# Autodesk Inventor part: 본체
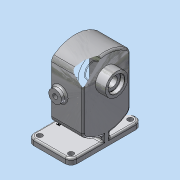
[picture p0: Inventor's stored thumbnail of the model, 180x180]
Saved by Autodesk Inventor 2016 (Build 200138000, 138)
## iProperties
Created: 2019-03
Part Number: 본체
Material: 알루미늄 6061
Document SubType Name: Modeling
Designer: Administrator
Density: 2.7 g/cm^3
Appearance: 알루미늄 - 평지
Mass: 1186.4 g
Surface Area: 720.893 cm^2
Volume: 439.408 cm^3
Author: Administrator
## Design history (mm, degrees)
sketch "스케치1"
  geometry: L1 (-36.5, -60)-(36.5, -60); L2 (36.5, -60)-(36.5, 60); L3 (36.5, 60)-(-36.5, 60); L4 (-36.5, 60)-(-36.5, -60); L5 (-36.5, -60)-(36.5, 60); L6 (36.5, -60)-(-36.5, 60); 1 further point
  constraints: 12 end point, 2 midpoint, 2 parallel, 1 horizontal, 1 perpendicular
  dimensions: "d0" = 73 distance of L2.end L3.end; "d1" = 120 distance between parallel lines of L1 L3
extrude "돌출1" new body sketch "스케치1" distance "d2" = 10; taper "d3" = 0 deg
node "작업 평면1"
sketch "스케치2"
  geometry: L1 (-78, 100)-(-78, 20); L2 (0, 0)-(0, 120) reference; L3 (-138, 100)-(-138, 20); L4 (-122.721, 100)-(-78, 100); L5 (0, 60)-(-138, 60); L6 (-122.721, 20)-(-78, 20); L7 (-33.279, 20)-(-78, 20); L8 (-78, 100)-(-33.279, 100); A1 r 60 centre (-78, 60) between (-122.721, 100) and (-122.721, 20); A2 r 60 centre (-78, 60) between (-33.279, 20) and (-33.279, 100); 2 further points
  constraints: 14 end point, 5 point on circle, 3 midpoint, 3 symmetric about line, 2 centre point, 2 coincident, 2 horizontal, 2 vertical, 1 horizontal alignment, 1 tangent, 1 other
  dimensions: "d5" = 78 distance between parallel lines of L2 L1; "d6" = 80 distance of L1.start L1.end; "d7" = 138 distance between parallel lines of L2 L3
extrude "돌출2" join sketch "스케치2" distance "d8" = 53; taper "d9" = 0 deg
sketch "스케치3"
  geometry: L1 (-78, -9.852)-(-78, 150.217); L2 (-100, -9.852)-(-100, 150.217); L3 (0, 60)-(-157.33, 60); C1 r 19 at (-100, 60)
  constraints: 6 end point, 2 point on line, 1 centre point, 1 horizontal, 1 parallel, 1 vertical
  dimensions: "d10" = 78 distance from line of L3.start L1; "d11" = 22 distance between parallel lines of L1 L2; "d12" = 38 diameter of C1
extrude "돌출3" join sketch "스케치3" distance "d13" = 17; taper "d14" = 0 deg
sketch "스케치4"
  geometry: L1 (36.5, -60)-(36.5, 60) reference; L2 (-6.5, 6)-(36.5, 6); L3 (36.5, 6)-(36.5, -6); L4 (36.5, -6)-(-6.5, -6); L5 (-6.5, -6)-(-6.5, 6); L6 (-77.559, 0)-(175.35, 0); L7 (-36.5, -60)-(36.5, -60) reference; 2 further points
  constraints: 10 end point, 2 horizontal, 2 parallel, 1 horizontal alignment, 1 midpoint, 1 perpendicular, 1 point on line
  dimensions: "d15" = 43 distance of L3.end L4.end; "d16" = 12 distance between parallel lines of L4 L2; "d17" = 60 distance between parallel lines of L7 L6
extrude "돌출4" join sketch "스케치4" stored distance "d18" = 17; taper "d19" = 0 deg
sketch "스케치5"
  geometry: L1 (33.279, 100)-(122.721, 100) reference; L2 (122.721, 20)-(33.279, 20) reference; L3 (56, 60)-(100, 60); L4 (56, 36)-(100, 36); L5 (100, 84)-(56, 84); A1 r 60 centre (78, 60) between (33.279, 100) and (33.279, 20) reference; A2 r 60 centre (78, 60) between (122.721, 20) and (122.721, 100) reference; A3 r 24 centre (56, 60) between (56, 84) and (56, 36); A4 r 24 centre (100, 60) between (100, 36) and (100, 84); 1 further point
  constraints: 8 end point, 4 point on circle, 4 tangent, 2 centre point, 1 horizontal, 1 midpoint, 1 parallel
  dimensions: "d20" = 48 diameter of A4; "d21" = 22 distance of A1.centre L3.end
extrude "돌출5" cut sketch "스케치5" distance "d22" = 29; taper "d23" = 0 deg
sketch "스케치6"
  geometry: L1 (-53.5, 119)-(-53.5, 81) reference; L2 (-53.5, 100)-(-12.5, 100); L3 (-12.5, 124)-(-12.5, 100) reference; L4 (-12.5, 56)-(-12.5, 100) reference; L5 (-12.5, 100)-(-12.5, 112.5); L6 (-12.5, 112.5)-(-27.5, 112.5); L7 (-27.5, 112.5)-(-27.5, 108.5); L8 (-27.5, 108.5)-(-46.2, 108.5); L9 (-46.2, 108.5)-(-46.2, 114); L10 (-46.2, 114)-(-53.5, 114); L11 (-53.5, 114)-(-53.5, 100); L12 (-12.5, 100)-(-53.5, 100); 1 further point
  constraints: 18 end point, 4 perpendicular, 2 collinear, 2 horizontal, 2 point on line, 1 midpoint
  dimensions: "d24" = 25 diameter of L6 L2; "d25" = 17 diameter of L8 L2; "d26" = 7.3 distance of L9.end L10.end; "d27" = 15 distance of L5.end L6.end; "d28" = 28 diameter of L10 L2
revolve "회전1" sketch "스케치6" stored, may be unused: angle "d29" = 90 deg
chamfer "모따기1" distance "d30" = 0.7; stored, may be unused: second distance "d31" = 2, angle "d32" = 30 deg
sketch "스케치7"
  geometry: L1 (55.758, 78)-(-149.717, 78); L2 (-36.5, 0)-(36.5, 0) reference; L3 (55.758, 56)-(-149.717, 56); L4 (-12.5, 56)-(-12.5, 100) reference; L5 (-12.5, 56)-(-12.5, 32) reference; L6 (-12.5, 56)-(-12.5, 68.5); L7 (-12.5, 68.5)-(-27.5, 68.5); L8 (-27.5, 68.5)-(-27.5, 56); L9 (-12.5, 56)-(-27.5, 56); 1 further point
  constraints: 12 end point, 2 horizontal, 2 point on line, 1 parallel, 1 perpendicular
  dimensions: "d33" = 78 distance between parallel lines of L2 L1; "d34" = 22 distance between parallel lines of L1 L3; "d35" = 25 diameter of L7 L3; "d36" = 15 distance of L6.end L7.end
revolve "회전2" sketch "스케치7" stored, may be unused: angle "d37" = 90 deg
sketch "스케치8"
  geometry: L1 (0, 89.443)-(0, 0) reference; L2 (0, 0)-(53, 0) reference; L3 (53, 89.443)-(53, 0) reference; L4 (0, 89.443)-(53, 89.443) reference; L5 (53, -33.279)-(53, -23.279) reference; L6 (-34.706, 44.721)-(156.464, 44.721); L7 (-20, -33.279)-(53, -33.279) reference; C1 r 11 at (14, 44.721); 1 further point
  constraints: 2 end point, 1 centre point, 1 horizontal, 1 point on line
  dimensions: "d39" = 78 distance between parallel lines of L7 L6; "d40" = 22 diameter of C1; "d85" = 14 distance from line of L1 C1.centre
extrude "돌출6" join sketch "스케치8" distance "d41" = 8; taper "d42" = 0 deg
hole "구멍1" diameter "d45" = 8.376; stored, may be unused: countersink angle "d49" = 90 deg, drill point angle "d51" = 118 deg; dims "d43" = 10, "d44" = 10, "d46" = 20, "d47" = 4, "d48" = 2, "d50" = 27.3
sketch "스케치9"
  geometry: L1 (100, 36)-(56, 36) reference; L2 (56, 84)-(100, 84) reference; L3 (33.279, 100)-(122.721, 100) reference; L4 (122.721, 20)-(33.279, 20) reference; L5 (56, 60)-(100, 60); L6 (56, 29)-(100, 29); L7 (100, 91)-(56, 91); L8 (78, 60)-(78, -16.701); C1 r 19 at (100, 60) reference; A1 r 24 centre (100, 60) between (100, 36) and (100, 84) reference; A2 r 24 centre (56, 60) between (56, 84) and (56, 36) reference; A3 r 60 centre (78, 60) between (33.279, 100) and (33.279, 20) reference; A4 r 60 centre (78, 60) between (122.721, 20) and (122.721, 100) reference; A5 r 31 centre (56, 60) between (56, 91) and (56, 29); A6 r 31 centre (100, 60) between (100, 29) and (100, 91); 5 further points
  constraints: 10 end point, 6 point on circle, 4 tangent, 2 centre point, 1 coincident, 1 horizontal, 1 horizontal alignment, 1 midpoint, 1 parallel, 1 symmetric about line, 1 vertical
  dimensions: "d52" = 22 horizontal distance of A3.centre point (100, 29); "d53" = 62 diameter of A6
hole "구멍2" sketch "스케치9" at (100, 29), (100, 91), (131, 60) diameter "d54" = 4.134; stored, may be unused: countersink angle "d58" = 90 deg, drill point angle "d60" = 118 deg; dims "d55" = 10, "d56" = 4, "d57" = 2, "d59" = 12
node "작업 평면2"
fillet "모깎기1" dims "d62" = 10
sketch "스케치10"
  geometry: A1 r 10 centre (26.5, 50) between (36.5, 50) and (26.5, 60) reference; A2 r 10 centre (26.5, -50) between (26.5, -60) and (36.5, -50) reference; A3 r 10 centre (-26.5, -50) between (-36.5, -50) and (-26.5, -60) reference; A4 r 10 centre (-26.5, 50) between (-26.5, 60) and (-36.5, 50) reference; 5 further points
  constraints: 4 coincident
hole "구멍3" sketch "스케치10" at (26.5, 50), (26.5, -50), (-26.5, -50), (-26.5, 50) diameter "d63" = 9; stored, may be unused: countersink angle "d67" = 90 deg, drill point angle "d69" = 0 deg; dims "d64" = 10, "d65" = 4, "d66" = 2, "d68" = 12
fillet "모깎기2" dims "d70" = 10
fillet "모깎기3" dims "d71" = 3
fillet "모깎기4" dims "d72" = 3
fillet "모깎기5" dims "d73" = 3
fillet "모깎기6" dims "d74" = 3
fillet "모깎기7" dims "d75" = 3
fillet "모깎기8" dims "d76" = 0.5
chamfer "모따기2" distance "d77" = 1; stored, may be unused: second distance "d78" = 2, angle "d79" = 30 deg
fillet "모깎기9" dims "d80" = 3
sketch "스케치11"
  geometry: L1 (26.5, 60)-(-26.5, 60) reference; L2 (-36.5, 50)-(-36.5, -50) reference; 2 further points
  constraints: 1 other
  dimensions: "d81" = 60 distance from line of L1 point (-26.5, 0); "d82" = 10 distance from line of L2 point (-26.5, 0)
feature "엠보싱1" sketch "스케치11" dims "d5" = 78, "d6" = 80, "d7" = 138, "d83" = 0.5, "d84" = 0
sketch "스케치12"
  geometry: L1 (0, 156.624)-(-70.333, 156.624); L2 (-70.333, 156.624)-(-70.333, 42.225); L3 (-70.333, 42.225)-(0, 42.225); L4 (0, 42.225)-(0, 156.624); 1 further point
  constraints: 8 end point, 2 parallel, 1 horizontal, 1 perpendicular
extrude "돌출7" cut sketch "스케치12" stored distance "d86" = 10; taper "d87" = 0 deg
node "솔리드1"
mirror "대칭1"
mirror "대칭2"
node "투영된 루프1"
node "투영된 루프2"
node "투영된 루프3"
other parameters: "d4" = -53, "d61" = -78
